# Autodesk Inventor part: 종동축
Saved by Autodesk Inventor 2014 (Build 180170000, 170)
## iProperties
Created: 2026-05
Part Number: 종동축
Material: 강철, 탄소
Document SubType Name: Modeling
Designer: dg
Density: 7.87 g/cm^3
Appearance: 반연마
Mass: 889.727 g
Surface Area: 209.523 cm^2
Volume: 113.053 cm^3
Author: jhkim
Creation Date: 2026-04-23
Sending System: Autodesk Inventor 2027
Preprocessor: ST-DEVELOPER v20.1
Author: dg
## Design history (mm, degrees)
node "종동축1"
node "솔리드1"
node "기준1"
